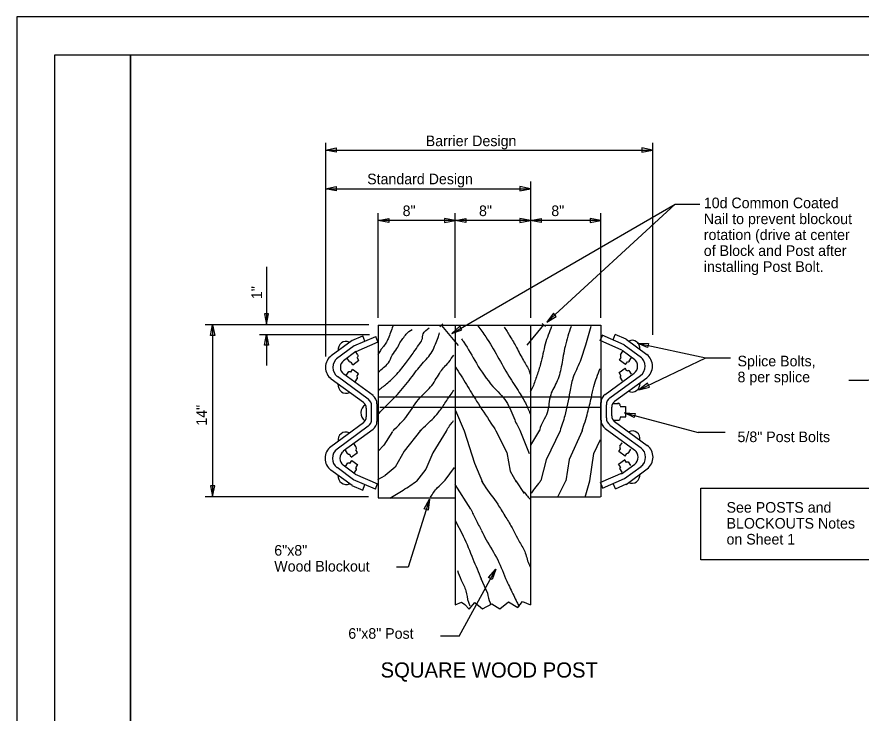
# Model space of a CAD drawing. Extents: x -0.7 to 89.2, y -3.6 to 22.
# Drawn here: x 0 to 11.14, y 12.81 to 22 of the extents above; entities that cross this region are included whole.
import ezdxf

# ---------------------------------------------------------------- set-up
doc = ezdxf.new("R2010")
doc.units = 0
for name, color, linetype in [('Default', 7, 'Continuous'), ('SH_Border', 7, 'Continuous'), ('ST_Text', 7, 'Continuous')]:
    doc.layers.add(name, color=color, linetype=linetype)

msp = doc.modelspace()

# ---------------------------------------------------------------- linework, layer by layer
at = {"layer": 'Default'}
for p, q in [((4.073, 20.338), (4.073, 17.917)), ((8.39, 20.338), (8.39, 17.802)), ((4.073, 20.243), (6.788, 20.243)), ((6.788, 20.243), (8.39, 20.243)), ((4.073, 19.732), (6.172, 19.732)), ((6.172, 19.732), (6.778, 19.732)), ((6.778, 19.826), (6.778, 19.281)), ((6.778, 19.826), (6.778, 18.027)), ((6.996, 17.973), (8.687, 19.529)), ((8.687, 19.529), (9.014, 19.529)), ((4.767, 18.027), (4.767, 19.408)), ((5.785, 18.027), (5.785, 19.408)), ((7.706, 18.027), (7.706, 19.408)), ((7.706, 19.313), (4.767, 19.313)), ((3.294, 18.7), (3.294, 17.94)), ((2.484, 17.94), (4.645, 17.94)), ((5.623, 17.948), (5.582, 17.91)), ((6.934, 17.953), (6.975, 17.916)), ((2.583, 17.935), (2.583, 17.212)), ((4.073, 17.917), (4.073, 17.786)), ((4.767, 17.933), (7.706, 17.933)), ((4.767, 17.933), (4.767, 15.651)), ((5.605, 17.928), (5.826, 17.663)), ((5.785, 17.933), (5.785, 14.239)), ((6.952, 17.934), (6.731, 17.669)), ((6.777, 17.933), (6.777, 14.239)), ((7.706, 17.933), (7.706, 15.665)), ((3.2, 17.809), (4.655, 17.809)), ((3.294, 17.809), (3.294, 17.4)), ((4.073, 17.786), (4.073, 17.519)), ((4.423, 17.729), (4.15, 17.529)), ((4.422, 17.73), (4.566, 17.792)), ((4.447, 17.657), (4.736, 17.783)), ((4.594, 17.722), (4.567, 17.792)), ((4.763, 17.713), (4.736, 17.782)), ((7.986, 17.601), (7.697, 17.728)), ((7.7, 17.728), (7.727, 17.797)), ((8.015, 17.672), (7.726, 17.798)), ((7.869, 17.738), (7.896, 17.807)), ((8.04, 17.745), (7.896, 17.808)), ((8.04, 17.745), (8.313, 17.545)), ((4.45, 17.658), (4.219, 17.489)), ((4.476, 17.586), (4.766, 17.712)), ((8.013, 17.673), (8.243, 17.505)), ((8.192, 17.692), (9.093, 17.499)), ((4.475, 17.586), (4.309, 17.463)), ((4.384, 17.455), (4.355, 17.501)), ((4.5, 17.538), (4.47, 17.585)), ((4.515, 17.467), (4.492, 17.503)), ((7.952, 17.469), (7.974, 17.505)), ((7.967, 17.54), (7.997, 17.587)), ((7.987, 17.601), (8.154, 17.479)), ((8.083, 17.457), (8.112, 17.503)), ((8.21, 17.079), (9.093, 17.499)), ((9.093, 17.499), (9.418, 17.499)), ((4.433, 17.409), (4.41, 17.445)), ((4.433, 17.409), (4.515, 17.468)), ((8.034, 17.411), (7.952, 17.47)), ((8.034, 17.411), (8.057, 17.447)), ((4.7, 17.002), (4.315, 17.283)), ((4.347, 17.269), (4.379, 17.319)), ((4.407, 17.31), (4.431, 17.348)), ((4.51, 17.291), (4.431, 17.348)), ((4.486, 17.252), (4.51, 17.29)), ((7.763, 17.018), (8.148, 17.298)), ((7.949, 17.306), (8.028, 17.363)), ((7.973, 17.267), (7.949, 17.305)), ((8.052, 17.325), (8.028, 17.363)), ((8.112, 17.284), (8.081, 17.334)), ((2.583, 17.212), (2.583, 15.67)), ((4.573, 16.912), (4.15, 17.221)), ((4.636, 16.957), (4.232, 17.252)), ((4.465, 17.183), (4.496, 17.232)), ((7.826, 16.973), (8.23, 17.267)), ((7.889, 16.928), (8.313, 17.236)), ((7.994, 17.198), (7.963, 17.247)), ((4.782, 16.986), (7.707, 16.986)), ((4.612, 16.721), (4.612, 16.835)), ((4.682, 16.691), (4.682, 16.865)), ((4.753, 16.662), (4.753, 16.894)), ((4.789, 16.85), (7.703, 16.85)), ((7.709, 16.677), (7.709, 16.91)), ((7.78, 16.707), (7.78, 16.88)), ((7.823, 16.849), (7.823, 16.849)), ((7.851, 16.736), (7.851, 16.85)), ((7.867, 16.9), (7.939, 16.9)), ((7.962, 16.86), (8.034, 16.86)), ((8.035, 16.72), (8.035, 16.859)), ((4.682, 16.773), (4.682, 16.783)), ((5.788, 16.807), (5.905, 16.538)), ((7.78, 16.788), (7.78, 16.799)), ((7.964, 16.72), (8.039, 16.72)), ((8.02, 16.776), (8.991, 16.516)), ((4.573, 16.644), (4.143, 16.328)), ((7.826, 16.614), (8.237, 16.313)), ((7.868, 16.676), (7.93, 16.676)), ((7.889, 16.659), (8.319, 16.344)), ((4.637, 16.599), (4.225, 16.297)), ((4.7, 16.554), (4.308, 16.267)), ((6.638, 16.547), (6.762, 16.236)), ((6.899, 16.547), (6.779, 16.35)), ((7.763, 16.569), (8.154, 16.282)), ((9.346, 16.516), (8.991, 16.516)), ((7.959, 16.333), (7.989, 16.38)), ((4.364, 16.237), (4.335, 16.283)), ((4.48, 16.32), (4.45, 16.367)), ((4.495, 16.25), (4.472, 16.285)), ((7.944, 16.263), (7.967, 16.298)), ((8.075, 16.25), (8.104, 16.296)), ((4.413, 16.191), (4.39, 16.227)), ((4.413, 16.191), (4.495, 16.25)), ((7.942, 16.099), (8.02, 16.156)), ((8.026, 16.204), (7.944, 16.263)), ((8.045, 16.118), (8.02, 16.157)), ((8.026, 16.204), (8.049, 16.24)), ((4.444, 15.892), (4.226, 16.051)), ((4.466, 15.967), (4.308, 16.082)), ((4.335, 16.065), (4.366, 16.115)), ((4.394, 16.105), (4.419, 16.144)), ((4.498, 16.086), (4.419, 16.143)), ((4.473, 16.047), (4.497, 16.085)), ((5.652, 15.885), (5.775, 16.052)), ((7.966, 16.06), (7.942, 16.098)), ((7.979, 15.969), (8.154, 16.097)), ((8.019, 15.907), (8.237, 16.066)), ((8.105, 16.078), (8.073, 16.128)), ((4.423, 15.816), (4.143, 16.02)), ((4.453, 15.978), (4.484, 16.027)), ((4.466, 15.967), (4.759, 15.839)), ((4.765, 15.895), (4.86, 15.946)), ((7.997, 15.983), (7.703, 15.854)), ((7.987, 15.992), (7.956, 16.04)), ((8.04, 15.831), (8.319, 16.035)), ((4.731, 15.766), (4.442, 15.892)), ((4.564, 15.754), (4.592, 15.827)), ((4.731, 15.766), (4.759, 15.84)), ((5.991, 15.502), (5.784, 15.828)), ((6.583, 15.876), (6.694, 15.712)), ((7.14, 15.665), (7.245, 15.876)), ((7.5, 15.66), (7.563, 15.876)), ((7.732, 15.781), (7.703, 15.855)), ((7.731, 15.781), (8.021, 15.908)), ((7.899, 15.77), (7.871, 15.842)), ((8.042, 15.832), (7.898, 15.769)), ((4.421, 15.817), (4.564, 15.754)), ((2.484, 15.67), (4.641, 15.67)), ((4.767, 15.651), (5.784, 15.651)), ((5.445, 15.634), (5.165, 14.74)), ((6.776, 15.665), (7.704, 15.665)), ((5.784, 15.354), (5.885, 15.16)), ((5.165, 14.74), (5.012, 14.74)), ((5.838, 13.828), (6.319, 14.71)), ((6.125, 14.589), (6.209, 14.394)), ((5.838, 13.828), (5.591, 13.828))]:
    msp.add_line(p, q, dxfattribs=at)
for points in [[(4.213, 20.215), (4.073, 20.243), (4.213, 20.271)], [(8.25, 20.215), (8.39, 20.243), (8.25, 20.271)], [(4.213, 19.704), (4.073, 19.732), (4.213, 19.76)], [(6.638, 19.704), (6.778, 19.732), (6.638, 19.76)], [(4.907, 19.285), (4.767, 19.313), (4.907, 19.341)], [(5.645, 19.285), (5.785, 19.313), (5.645, 19.341)], [(5.925, 19.285), (5.785, 19.313), (5.925, 19.341)], [(6.638, 19.285), (6.778, 19.313), (6.638, 19.341)], [(6.918, 19.285), (6.778, 19.313), (6.918, 19.341)], [(7.566, 19.285), (7.706, 19.313), (7.566, 19.341)], [(3.266, 18.08), (3.294, 17.94), (3.322, 18.08)], [(7.081, 18.088), (6.996, 17.973), (7.118, 18.046)], [(2.555, 17.795), (2.583, 17.935), (2.611, 17.795)], [(5.846, 17.917), (5.739, 17.823), (5.874, 17.869)], [(3.266, 17.669), (3.294, 17.809), (3.322, 17.669)], [(8.323, 17.636), (8.192, 17.692), (8.335, 17.69)], [(8.324, 17.166), (8.21, 17.079), (8.348, 17.115)], [(8.147, 16.711), (8.02, 16.776), (8.162, 16.764)], [(2.555, 15.81), (2.583, 15.67), (2.611, 15.81)], [(9.026, 15.782), (11.81, 15.782), (11.81, 14.833), (9.026, 14.833)], [(5.375, 15.509), (5.445, 15.634), (5.428, 15.492)], [(6.225, 14.602), (6.319, 14.71), (6.274, 14.574)]]:
    msp.add_lwpolyline(points, close=True, dxfattribs=at)
for points in [[(5.739, 17.823), (8.687, 19.529)], [(12.81, 17.692), (11.229, 17.203), (10.979, 17.203)], [(4.959, 16.53), (4.841, 16.346), (4.77, 16.267)], [(5.325, 16.542), (5.112, 16.267), (4.994, 16.056), (4.86, 15.946)], [(5.666, 16.531), (5.49, 16.245), (5.398, 16.03), (5.274, 15.873)], [(5.905, 16.538), (6.038, 16.109), (6.143, 15.858)], [(6.322, 16.538), (6.468, 16.249), (6.512, 16.003), (6.591, 15.863)], [(7.168, 16.538), (6.986, 16.153), (6.915, 15.881)], [(7.461, 16.538), (7.288, 16.157), (7.245, 15.876)], [(7.563, 15.876), (7.613, 16.236), (7.701, 16.424)], [(5.785, 14.239), (5.866, 14.277), (5.912, 14.246), (5.97, 14.185), (6.044, 14.273), (6.143, 14.189), (6.267, 14.255), (6.375, 14.189), (6.487, 14.281), (6.611, 14.207), (6.673, 14.286), (6.777, 14.239)]]:
    msp.add_lwpolyline(points, dxfattribs=at)
for centre, major_axis, start_param, end_param in [((4.342, 17.61), (0, -0.107), 2.687211, 4.851441), ((8.12, 17.626), (0, -0.107), 1.431744, 3.595974), ((4.25, 17.375), (0, -0.187), 3.747084, 5.680264), ((4.313, 17.375), (0, -0.15), 3.747137, 5.680324), ((4.484, 17.525), (0, 0.0198), 3.70437, 5.352473), ((7.983, 17.527), (0, 0.0198), 0.930712, 2.578815), ((8.15, 17.39), (0, -0.15), 0.602861, 2.536048), ((8.212, 17.39), (0, -0.187), 0.602921, 2.536101), ((4.375, 17.375), (0, -0.112), 3.747102, 5.680297), ((4.397, 17.466), (0, -0.0195), 5.247458, 6.879592), ((8.07, 17.468), (0, -0.0195), 5.686779, 7.318912), ((8.087, 17.391), (0, -0.112), 0.602888, 2.536083), ((4.391, 17.296), (0, 0.021), 5.452301, 7.118326), ((8.068, 17.311), (0, 0.021), 5.448045, 7.11407), ((4.477, 17.234), (0, 0.021), 4.196406, 5.73538), ((7.982, 17.249), (0, 0.021), 0.547805, 2.086779), ((8.117, 17.163), (0, -0.115), 5.852054, 7.925719), ((4.345, 17.148), (0, -0.115), 4.640651, 6.714317), ((4.576, 16.865), (0, 0.112), 4.712389, 5.68034), ((4.629, 16.894), (0, 0.131), 4.712389, 5.680267), ((7.833, 16.91), (0, 0.131), 0.602918, 1.570796), ((7.886, 16.88), (0, 0.112), 0.602846, 1.570796), ((4.652, 16.773), (0, -0.12), 3.613765, 5.74142), ((4.523, 16.835), (0, 0.0937), 4.712389, 5.680377), ((7.94, 16.85), (0, 0.0937), 0.602808, 1.570796), ((7.937, 16.871), (0, -0.0298), 2.729343, 3.43401), ((7.936, 16.87), (0, 0.03), 4.574534, 6.237266), ((7.937, 16.871), (0, -0.0298), 1.431351, 1.439211), ((4.523, 16.721), (0, -0.0937), 0.605563, 1.570796), ((7.94, 16.736), (0, -0.0937), 4.712389, 5.677623), ((4.576, 16.691), (0, -0.112), 0.605651, 1.570796), ((4.629, 16.662), (0, -0.131), 0.605566, 1.570796), ((7.833, 16.677), (0, -0.131), 4.712389, 5.677619), ((7.886, 16.707), (0, -0.112), 4.712389, 5.677535), ((7.935, 16.708), (0, -0.0326), 6.093782, 8.000338), ((4.339, 16.413), (0, -0.107), 2.687211, 4.851441), ((8.123, 16.429), (0, -0.107), 1.431744, 3.595974), ((4.244, 16.174), (0, -0.187), 3.747091, 5.68028), ((4.306, 16.174), (0, -0.15), 3.747115, 5.680355), ((4.464, 16.307), (0, 0.0198), 3.70437, 5.352473), ((7.975, 16.32), (0, 0.0198), 0.930712, 2.578815), ((8.094, 16.19), (0, -0.112), 0.602927, 2.536083), ((8.156, 16.189), (0, -0.15), 0.602831, 2.53607), ((8.219, 16.189), (0, -0.187), 0.602905, 2.536094), ((4.369, 16.174), (0, -0.112), 3.747102, 5.680258), ((4.377, 16.248), (0, -0.0195), 5.247458, 6.879592), ((8.062, 16.261), (0, -0.0195), 5.686779, 7.318912), ((4.379, 16.091), (0, 0.021), 5.452301, 7.118326), ((4.464, 16.029), (0, 0.021), 4.196406, 5.73538), ((7.975, 16.042), (0, 0.021), 0.547805, 2.086779), ((8.06, 16.104), (0, 0.021), 5.448045, 7.11407), ((4.345, 15.944), (0, -0.115), 4.640651, 6.714317), ((8.117, 15.96), (0, -0.115), 5.852054, 7.925719)]:
    msp.add_ellipse(centre, major_axis=major_axis, ratio=0.944544, start_param=start_param, end_param=end_param, dxfattribs=at)
for points in [[(4.962, 17.919), (4.899, 17.753), (4.87, 17.695), (4.827, 17.637), (4.798, 17.599), (4.765, 17.541)], [(4.768, 17.068), (4.877, 17.156), (5.016, 17.287), (5.143, 17.445), (5.241, 17.579), (5.306, 17.672), (5.346, 17.737), (5.364, 17.818), (5.441, 17.898)], [(4.768, 17.31), (4.837, 17.372), (4.903, 17.433), (4.954, 17.537), (5.016, 17.622), (5.055, 17.699), (5.095, 17.756), (5.139, 17.814), (5.215, 17.874)], [(4.772, 16.764), (4.87, 16.864), (5.023, 17.018), (5.197, 17.229), (5.35, 17.422), (5.48, 17.583), (5.524, 17.679), (5.56, 17.768), (5.578, 17.83)], [(6.083, 17.924), (6.188, 17.778), (6.344, 17.52), (6.493, 17.258), (6.631, 17.043), (6.722, 16.885), (6.78, 16.743)], [(6.432, 17.907), (6.508, 17.785), (6.595, 17.635), (6.686, 17.466), (6.762, 17.324), (6.773, 17.285)], [(7.057, 17.915), (6.974, 17.683), (6.912, 17.42), (6.863, 17.267), (6.809, 17.118), (6.776, 17.048)], [(7.314, 17.916), (7.235, 17.652), (7.19, 17.411), (7.132, 17.197), (7.045, 17.013), (6.999, 16.776), (6.9, 16.553), (6.897, 16.538)], [(7.577, 17.914), (7.504, 17.669), (7.433, 17.451), (7.338, 17.232), (7.297, 17.052), (7.231, 16.737), (7.168, 16.538)], [(5.868, 17.75), (5.897, 17.708), (6.065, 17.428), (6.283, 17.124), (6.457, 16.924), (6.57, 16.681), (6.643, 16.538)], [(4.965, 16.538), (5.153, 16.741), (5.324, 16.979), (5.477, 17.137), (5.593, 17.318), (5.699, 17.445), (5.767, 17.537)], [(5.788, 17.381), (5.934, 17.147), (6.068, 16.928), (6.257, 16.639), (6.322, 16.538)], [(7.461, 16.538), (7.533, 16.776), (7.582, 16.978), (7.615, 17.122), (7.698, 17.359)], [(5.32, 16.538), (5.415, 16.626), (5.579, 16.799), (5.673, 16.937), (5.767, 17.072)], [(5.666, 16.531), (5.68, 16.556), (5.764, 16.672)], [(4.921, 15.649), (5.099, 15.756), (5.279, 15.876)], [(5.459, 15.66), (5.549, 15.787), (5.64, 15.872), (5.657, 15.891)], [(6.131, 15.876), (6.168, 15.818), (6.346, 15.568), (6.439, 15.416)], [(6.915, 15.881), (6.884, 15.84), (6.817, 15.757), (6.784, 15.708)], [(6.69, 15.731), (6.74, 15.674), (6.777, 15.631)], [(5.99, 15.504), (6.057, 15.367), (6.132, 15.22)], [(6.43, 15.431), (6.52, 15.284), (6.635, 15.069), (6.71, 14.925), (6.764, 14.763), (6.776, 14.741)], [(5.881, 15.168), (5.891, 15.148), (6.019, 14.846), (6.128, 14.582)], [(6.133, 15.218), (6.193, 15.1), (6.346, 14.833), (6.466, 14.553), (6.557, 14.364), (6.598, 14.277), (6.627, 14.22)], [(5.814, 14.695), (5.864, 14.568), (5.926, 14.424), (5.959, 14.275), (5.98, 14.227)], [(6.209, 14.394), (6.247, 14.268), (6.259, 14.242)]]:
    msp.add_spline(points, degree=3, dxfattribs=at)
at = {"layer": 'SH_Border'}
for points in [[(0.5, 21.5), (1.5, 21.5), (1.5, 0.5), (0.5, 0.5)], [(1.5, 21.5), (33.5, 21.5), (33.5, 0.5), (1.5, 0.5)]]:
    msp.add_lwpolyline(points, close=True, dxfattribs=at)
at = {"layer": 'ST_Text'}
msp.add_lwpolyline([(0, 0), (34, 0), (34, 22), (0, 22)], close=True, dxfattribs=at)

# ---------------------------------------------------------------- texts
at = {"layer": 'Default'}
for s, height, p in [('Barrier Design', 0.14, (5.396, 20.294)), ('Standard Design', 0.14, (4.623, 19.791)), ('10d Common Coated', 0.14, (9.066, 19.475)), ('  8"', 0.14, (4.987, 19.371)), ('  8"', 0.14, (5.995, 19.371)), ('  8"', 0.14, (6.949, 19.371)), ('Nail to prevent blockout', 0.14, (9.066, 19.265)), ('rotation (drive at center', 0.14, (9.066, 19.055)), ('of Block and Post after', 0.14, (9.066, 18.845)), ('installing Post Bolt.', 0.14, (9.066, 18.635)), ('Splice Bolts,', 0.14, (9.511, 17.388)), ('8 per splice', 0.14, (9.511, 17.178)), ('5/8" Post Bolts', 0.14, (9.511, 16.388)), ('See POSTS and', 0.14, (9.366, 15.457)), ('BLOCKOUTS Notes', 0.14, (9.366, 15.247)), ('on Sheet 1', 0.14, (9.366, 15.037)), ('6"x8"', 0.14, (3.397, 14.89)), ('Wood Blockout', 0.14, (3.397, 14.68)), ('6"x8" Post', 0.14, (4.374, 13.793)), ('SQUARE WOOD POST', 0.2, (4.8, 13.281))]:
    msp.add_text(s, height=height, dxfattribs=at).set_placement(p)
for s, p in [('1"', (3.235, 18.276)), ('14" ', (2.508, 16.605))]:
    msp.add_text(s, height=0.14, rotation=90, dxfattribs=at).set_placement(p)

doc.saveas('drawing.dxf')
